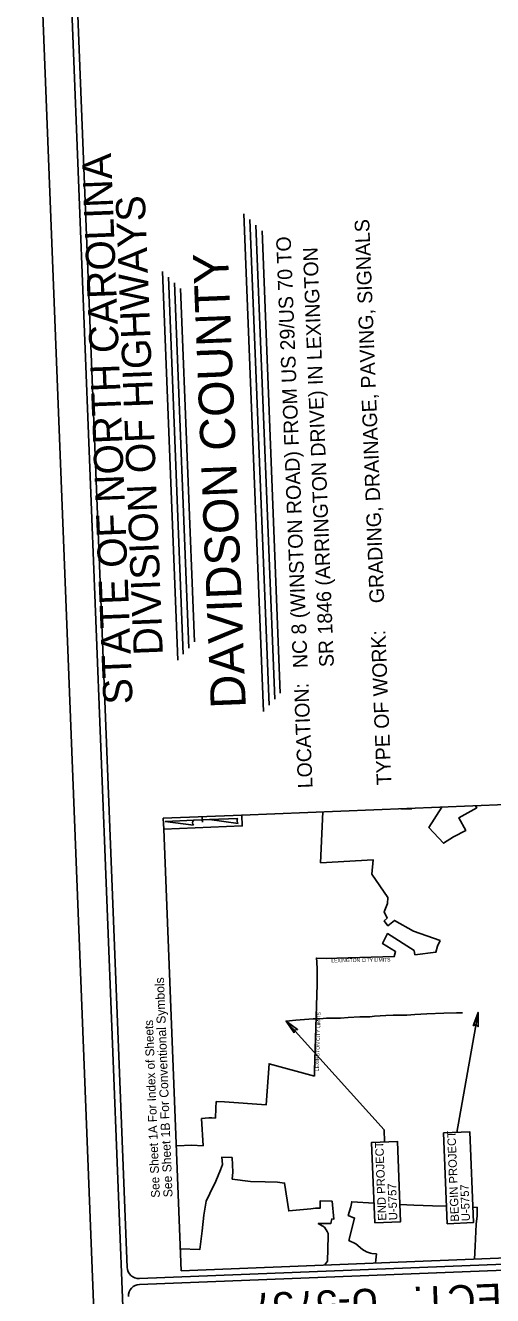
# Model space of a CAD drawing. Extents: x 1624323 to 1631382, y 753034 to 769560.
# Drawn here: x 1624323 to 1626744, y 758593 to 765176 of the extents above; entities that cross this region are included whole.
import ezdxf

# ---------------------------------------------------------------- set-up
doc = ezdxf.new("R2010")
doc.units = 0
for name, color, linetype in [('Default', 7, 'Continuous'), ('Old_Level_1', 7, 'Continuous'), ('Old_Level_12', 7, 'Continuous'), ('Old_Level_2', 7, 'Continuous'), ('Old_Level_9', 7, 'Continuous'), ('Prop DSN Text', 7, 'Continuous'), ('Prop Grid Mask', 7, 'Continuous'), ('Prop Terminator CELL', 7, 'Continuous'), ('Sheet Data Field CELL', 7, 'Continuous'), ('Sheet Plot Border Outside CELL', 7, 'Continuous'), ('Sheet Title CELL', 7, 'Continuous'), ('Sheet Title Data Points CELL', 7, 'Continuous')]:
    doc.layers.add(name, color=color, linetype=linetype)

msp = doc.modelspace()

# ---------------------------------------------------------------- linework, layer by layer
at = {"layer": 'Default'}
msp.add_line((1626322.2, 761112.9), (1626322.2, 761112.9), dxfattribs=at)
msp.add_lwpolyline([(1626322.2, 761112.9), (1626327, 761118.2)], dxfattribs=at)
at = {"layer": 'Old_Level_1'}
for p, q in [((1624523.8, 762423.9), (1624523.8, 762423.9)), ((1625815, 760026.8), (1625769.7, 760024.4))]:
    msp.add_line(p, q, dxfattribs=at)
for points in [[(1625129.8, 758721.3), (1625039.5, 761010.7), (1625446.6, 761026.7), (1625444.4, 761083.4), (1626812, 761137.4), (1626904.5, 758791.2)], [(1625037.3, 761067.4), (1625039.5, 761010.7), (1625446.6, 761026.7), (1625444.4, 761083.4)]]:
    msp.add_lwpolyline(points, close=True, dxfattribs=at)
for points in [[(1625769.7, 760024.4), (1625724.9, 760020.3), (1625673.8, 760015.2)], [(1626588.7, 760058.1), (1626583.2, 760057.7), (1626556.8, 760057.9), (1626491.3, 760055.6), (1626403.1, 760053.6), (1626341.1, 760049.7), (1626299.6, 760046.1), (1626244.9, 760045.3), (1626229.4, 760046.6), (1626191.5, 760044.4), (1626132.6, 760041.4), (1626107.5, 760038), (1626056.4, 760037.4), (1625995.7, 760034.5), (1625956.1, 760029.9), (1625883.5, 760030.5), (1625847.9, 760026.4), (1625815, 760026.8)]]:
    msp.add_lwpolyline(points, dxfattribs=at)
at = {"layer": 'Old_Level_2'}
for p, q in [((1625047.4, 761050.6), (1625198, 761056.6)), ((1625047.4, 761050.6), (1625047.4, 761050.5)), ((1625047.4, 761050.6), (1625047.4, 761050.5)), ((1625194.4, 761030.4), (1625047.4, 761050.5)), ((1625276.1, 761059.7), (1625193.6, 761056.4)), ((1625198, 761056.6), (1625193.7, 761056.4)), ((1625240, 761045.8), (1625239, 761071)), ((1625239.6, 761056.8), (1625240, 761045.6)), ((1625424.3, 761065.7), (1625276.1, 761059.7)), ((1625276.1, 761059.7), (1625425.9, 761039.2)), ((1625240, 761045.6), (1625240.1, 761045.5))]:
    msp.add_line(p, q, dxfattribs=at)
for centre, start_param, end_param in [((1625195.5, 761043.5), 0.216388, 2.908219), ((1625425.9, 761052.6), 0.201328, 3.141593)]:
    msp.add_ellipse(centre, major_axis=(-0.4, 13.3), ratio=0.461098, start_param=start_param, end_param=end_param, dxfattribs=at)
at = {"layer": 'Old_Level_9'}
for p, q in [((1626267.9, 761115.9), (1626322.2, 761112.9)), ((1625851.8, 760835.3), (1625864.3, 761100)), ((1626472.9, 760433.8), (1626334.9, 760481.5))]:
    msp.add_line(p, q, dxfattribs=at)
for points in [[(1626322.2, 761112.9), (1626327, 761118.2)], [(1626480.5, 761124.3), (1626413.7, 761019.4), (1626489.7, 760937.4), (1626541.2, 760970.5), (1626605.1, 761003.5), (1626569.1, 761069), (1626661.7, 761121.1), (1626654.9, 761131.2)], [(1626334.9, 760481.5), (1626236.2, 760537.4), (1626201.4, 760509.6), (1626182.9, 760535.1), (1626196.8, 760549), (1626182.8, 760581.4), (1626199.1, 760625.4), (1626201.4, 760655.5), (1626119, 760776), (1626125.7, 760850.7), (1625851.8, 760835.3)], [(1625937.1, 760341.7), (1626234.2, 760349.9), (1626240.9, 760376.4), (1626173.9, 760417.4), (1626199.8, 760469), (1626338.2, 760381.1), (1626341.1, 760359.2), (1626450.5, 760372.4), (1626459, 760403.7), (1626472.9, 760433.8)], [(1625820.6, 759729.4), (1625820.9, 759757.3), (1625834.9, 760207.2), (1625835.5, 760283.1), (1625834, 760322.5), (1625830.9, 760341.8), (1625884.4, 760340.5), (1625937.1, 760341.7)], [(1625310.7, 759599.4), (1625354.2, 759596.2), (1625571, 759581.7), (1625585.7, 759794.6), (1625820.6, 759729.4)], [(1625104.2, 759368.9), (1625110.2, 759369.4), (1625184.1, 759373), (1625243.5, 759369.4), (1625236.2, 759510.3), (1625273.8, 759513.6), (1625288.9, 759513.6), (1625307.5, 759512.8), (1625309.1, 759564.6), (1625310.7, 759599.4)], [(1625394.2, 759196.7), (1625397.8, 759232.7), (1625394.1, 759308.3), (1625340.1, 759309.4), (1625344.4, 759271.8), (1625333.1, 759244.1), (1625309.9, 759186.6), (1625278.4, 759121.1), (1625259.1, 759081.4), (1625248.3, 759009.4), (1625239.3, 758928.4), (1625226.3, 758831.6), (1625125.3, 758834.4)], [(1625629.8, 759179.9), (1625565.4, 759181.6), (1625489.9, 759184.9), (1625394.2, 759196.7)], [(1625872.4, 758750.5), (1625872.6, 758751.2), (1625887.6, 758771.6), (1625892.4, 758900.3), (1625892.3, 758914), (1625887, 758924.8), (1625872.2, 758948), (1625840.7, 758966.9), (1625906.2, 758966.9), (1625911.5, 758990.5), (1625921.3, 758989.4), (1625911.8, 759081.8), (1625849.6, 759083.7), (1625851.3, 759046.2), (1625826.5, 759045.6), (1625802.5, 759041.8), (1625687.3, 759031.7), (1625666, 759176.2), (1625629.8, 759179.9)], [(1626129.5, 759072), (1626014.5, 759079), (1626008.7, 759052.9)], [(1626008.7, 759052.9), (1625995.6, 759007.2), (1626028.4, 758994.6), (1625999.5, 758878.8), (1626034.9, 758861.6), (1626069, 758831.9), (1626091.3, 758818.7), (1626111.1, 758812.3), (1626118.3, 758810.6), (1626142, 758809.1), (1626139.7, 758778.5), (1626137.2, 758761)], [(1626505.4, 759055.9), (1626432.1, 759057.6), (1626335.6, 759062.2), (1626264.1, 759065)], [(1626650.6, 758781.2), (1626653.2, 758849.3), (1626659.5, 758963.1), (1626663.3, 759006.7), (1626664.5, 759049.4), (1626641.7, 759050.3)]]:
    msp.add_lwpolyline(points, dxfattribs=at)
at = {"layer": 'Prop DSN Text'}
for p, q in [((1626669.1, 760060.6), (1626558.3, 759438.5)), ((1625673.8, 760015.2), (1626181.7, 759452.4)), ((1626181.7, 759452.4), (1626184.2, 759388.9))]:
    msp.add_line(p, q, dxfattribs=at)
at = {"layer": 'Prop Grid Mask'}
for points in [[(1626509, 758965.3), (1626490.4, 759435.9), (1626626.3, 759441.2), (1626644.8, 758970.7)], [(1626133.5, 758970.2), (1626117.1, 759386.2), (1626251.2, 759391.5), (1626267.6, 758975.5)]]:
    msp.add_lwpolyline(points, close=True, dxfattribs=at)
at = {"layer": 'Prop Terminator CELL'}
for points in [[(1626644, 759991.2), (1626669.1, 760060.6), (1626669, 759986.3), (1626657.9, 759997.8)], [(1625715, 759954), (1625673.8, 760015.2), (1625733.7, 759971.3), (1625717.9, 759969.1)]]:
    msp.add_lwpolyline(points, close=True, dxfattribs=at)
at = {"layer": 'Sheet Plot Border Outside CELL'}
msp.add_lwpolyline([(1624322.9, 767519.9), (1624724.8, 757327.8), (1631382.3, 757590.3), (1630980.3, 767782.4)], close=True, dxfattribs=at)
at = {"layer": 'Sheet Title CELL'}
for p, q in [((1625556.5, 761620.5), (1625454.9, 764198.8)), ((1625585.6, 761651.9), (1625486.4, 764169.7)), ((1625614.8, 761683.4), (1625517.8, 764140.6)), ((1625643.7, 761714.9), (1625549.3, 764111.6)), ((1625112.1, 761885.7), (1625032.6, 763899.6)), ((1625141.1, 761917.2), (1625064.2, 763870.6)), ((1625170.3, 761948.7), (1625095.6, 763841.5)), ((1625199.3, 761980.1), (1625127, 763812.4)), ((1629967.5, 758880.3), (1624913.8, 758681)), ((1631088.4, 758894.1), (1624915, 758650.7))]:
    msp.add_line(p, q, dxfattribs=at)
for points in [[(1624480.6, 767362.5), (1624833.8, 758405)], [(1624512.1, 767333.4), (1624851, 758739.2)]]:
    msp.add_lwpolyline(points, dxfattribs=at)
for centre, start, end in [((1624911.2, 758741.5), 182.25819, 272.25819), ((1624917.1, 758590.2), 92.25819, 182.25819)]:
    msp.add_arc(centre, 60.6, start, end, dxfattribs=at)
at = {"layer": 'Sheet Title Data Points CELL'}
for p, q in [((1625715.5, 763655), (1625715.5, 763655)), ((1625415.2, 762915.5), (1625415.2, 762915.5))]:
    msp.add_line(p, q, dxfattribs=at)

# ---------------------------------------------------------------- texts
at = {"layer": 'Default'}
for rotation, p in [(0.89071, (1625908.4, 760319.7)), (88.26, (1625843.5, 759755.9))]:
    msp.add_text('LEXINGTON CITY LIMITS', height=18.75, rotation=rotation, dxfattribs=at).set_placement(p)
at = {"layer": 'Old_Level_12'}
msp.add_text('See Sheet 1B For Conventional Symbols', height=46.904, rotation=92.25831, dxfattribs=at).set_placement((1625085.6, 759103.5))
at = {"layer": 'Prop DSN Text'}
for s, p in [('BEGIN PROJECT', (1626570.2, 758977)), ('END PROJECT', (1626194, 758981.8)), ('U-5757', (1626251.2, 758984)), ('U-5757', (1626627.4, 758979.2))]:
    msp.add_text(s, height=43.61, rotation=92.25819, dxfattribs=at).set_placement(p)
at = {"layer": 'Sheet Data Field CELL'}
for s, height, p in [('GRADING, DRAINAGE, PAVING, SIGNALS', 75.713, (1626182.7, 762182.7)), ('NC 8 (WINSTON ROAD) FROM US 29/US 70 TO ', 75.713, (1625785.7, 761846.4)), ('SR 1846 (ARRINGTON DRIVE) IN LEXINGTON', 75.713, (1625921.9, 761851.7)), ('DAVIDSON COUNTY', 181.71, (1625465.5, 761639.1))]:
    msp.add_text(s, height=height, rotation=92.25819, dxfattribs=at).set_placement(p)
at = {"layer": 'Sheet Title CELL'}
for s, height, rotation, p in [('STATE OF NORTH CAROLINA', 151.425, 92.25819, (1624878.9, 761659.5)), ('DIVISION OF HIGHWAYS', 151.425, 92.25819, (1625035.5, 761913.6)), ('TYPE OF WORK:', 75.713, 92.25819, (1626219.9, 761239.6)), ('LOCATION: ', 75.71, 92.25819, (1625811.3, 761223.5)), ('See Sheet 1A For Index of Sheets', 45.428, 92.25819, (1625020.1, 759100.9)), ('TIP PROJECT:', 151.425, 182.25819, (1627698.9, 758691.5)), ('U-5757', 151.43, 182.25819, (1626152.1, 758630.5))]:
    msp.add_text(s, height=height, rotation=rotation, dxfattribs=at).set_placement(p)

doc.saveas('drawing.dxf')
